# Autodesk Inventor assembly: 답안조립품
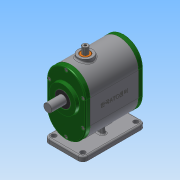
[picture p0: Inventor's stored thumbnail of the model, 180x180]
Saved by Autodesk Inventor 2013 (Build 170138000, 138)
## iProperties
Created: 2016-12
Part Number: 답안조립품
Document SubType Name: Assembly
Designer: Administrator
Author: Administrator
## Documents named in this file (14)
- C:\Users\Administrator\Desktop\361208V1029\답안조립품.iam
- C:\Users\Administrator\Desktop\361208V1029\본체.ipt
- C:\Users\Administrator\Desktop\361208V1029\가변스프링.ipt
- C:\Users\Administrator\Desktop\361208V1029\뒤커버.ipt
- C:\Users\Administrator\Desktop\361208V1029\메인축.ipt
- C:\Users\Administrator\Desktop\361208V1029\베어링 608.ipt
- C:\Users\Administrator\Desktop\361208V1029\베어링 6003.ipt
- C:\Users\Administrator\Desktop\361208V1029\볼트 M4.ipt
- C:\Users\Administrator\Desktop\361208V1029\부시.ipt
- C:\Users\Administrator\Desktop\361208V1029\서브축.ipt
- C:\Users\Administrator\Desktop\361208V1029\슬라이더.ipt
- C:\Users\Administrator\Desktop\361208V1029\앞커버.ipt
- C:\Users\Administrator\Desktop\361208V1029\오일실 8 22 7.ipt
- C:\Users\Administrator\Desktop\361208V1029\오일실 17 32 8.ipt
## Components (1 placed, 1 different names)
1. 가변스프링:1
